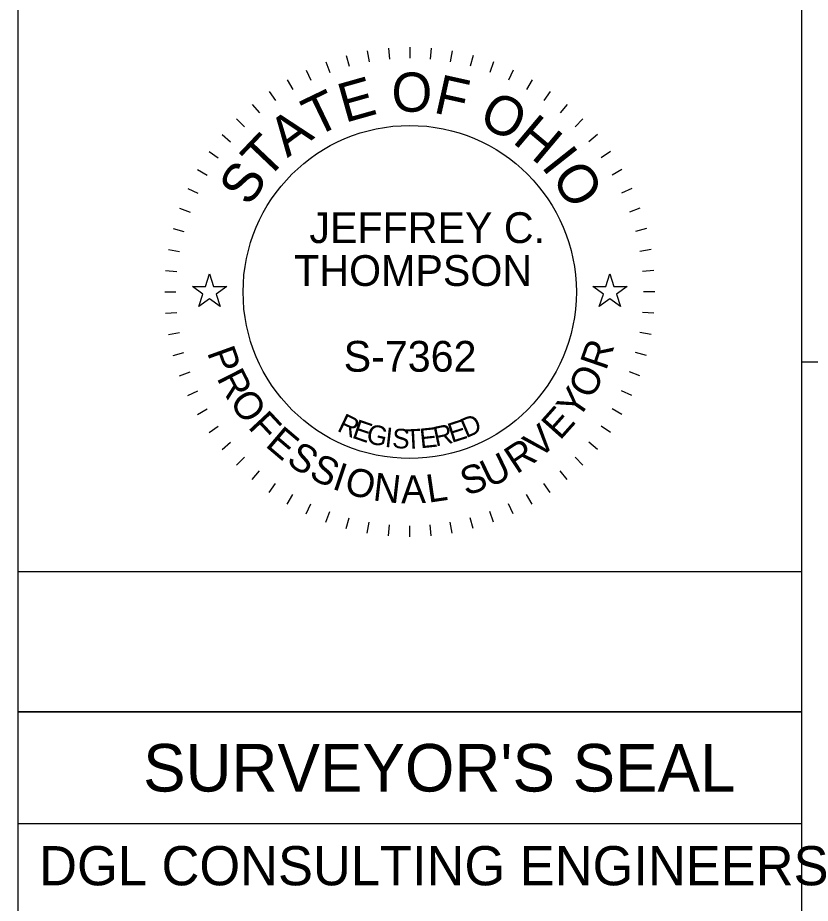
# Model space of a CAD drawing. Extents: x -10.5 to 54.7, y 0 to 22.
# Drawn here: x 29.2 to 32.03, y 3.066 to 6.23 of the extents above; entities that cross this region are included whole.
import ezdxf

# ---------------------------------------------------------------- set-up
doc = ezdxf.new("R2010")
doc.units = 0
for name, color, linetype in [('Default', 7, 'Continuous'), ('SH_Border', 7, 'Continuous'), ('SH_Data', 7, 'Continuous')]:
    doc.layers.add(name, color=color, linetype=linetype)

msp = doc.modelspace()

# ---------------------------------------------------------------- linework, layer by layer
at = {"layer": 'Default'}
for points in [[(29.8236, 5.27), (29.8705, 5.27), (29.885, 5.3145), (29.8995, 5.27), (29.9464, 5.27), (29.9085, 5.2424), (29.923, 5.1978), (29.885, 5.2254), (29.847, 5.1978), (29.8615, 5.2424)], [(31.2536, 5.27), (31.3005, 5.27), (31.315, 5.3145), (31.3295, 5.27), (31.3764, 5.27), (31.3385, 5.2424), (31.353, 5.1978), (31.315, 5.2254), (31.277, 5.1978), (31.2915, 5.2424)]]:
    msp.add_lwpolyline(points, close=True, dxfattribs=at)
at = {"layer": 'SH_Border'}
for p, q in [((32, 0.5), (32, 21.5)), ((32, 5), (33.5, 5))]:
    msp.add_line(p, q, dxfattribs=at)
at = {"layer": 'SH_Data'}
for p, q in [((29.2, 7), (29.2, 3.75)), ((32, 3.75), (32, 7)), ((30.4481, 6.1117), (30.455, 6.0723)), ((30.5237, 6.1217), (30.5272, 6.0818)), ((30.6, 6.125), (30.6, 6.085)), ((30.6763, 6.1217), (30.6728, 6.0818)), ((30.7519, 6.1117), (30.745, 6.0723)), ((30.3735, 6.0952), (30.3839, 6.0565)), ((30.8265, 6.0952), (30.8161, 6.0565)), ((30.3007, 6.0722), (30.3144, 6.0346)), ((30.8993, 6.0722), (30.8856, 6.0346)), ((30.2302, 6.043), (30.2471, 6.0068)), ((30.9698, 6.043), (30.9529, 6.0068)), ((30.1625, 6.0078), (30.1825, 5.9731)), ((31.0375, 6.0078), (31.0175, 5.9731)), ((30.0981, 5.9668), (30.1211, 5.934)), ((31.1019, 5.9668), (31.0789, 5.934)), ((30.0376, 5.9203), (30.0633, 5.8896)), ((31.1624, 5.9203), (31.1367, 5.8896)), ((29.9813, 5.8687), (30.0096, 5.8404)), ((31.2187, 5.8687), (31.1904, 5.8404)), ((29.9297, 5.8124), (29.9604, 5.7867)), ((31.2703, 5.8124), (31.2396, 5.7867)), ((29.8832, 5.7519), (29.916, 5.7289)), ((31.3168, 5.7519), (31.284, 5.7289)), ((29.8422, 5.6875), (29.8769, 5.6675)), ((31.3578, 5.6875), (31.3231, 5.6675)), ((29.807, 5.6198), (29.8432, 5.6029)), ((31.393, 5.6198), (31.3568, 5.6029)), ((29.7778, 5.5493), (29.8154, 5.5356)), ((31.4222, 5.5493), (31.3846, 5.5356)), ((29.7548, 5.4765), (29.7935, 5.4661)), ((31.4452, 5.4765), (31.4065, 5.4661)), ((29.7383, 5.4019), (29.7777, 5.395)), ((31.4617, 5.4019), (31.4223, 5.395)), ((29.7283, 5.3263), (29.7682, 5.3228)), ((31.4717, 5.3263), (31.4318, 5.3228)), ((29.725, 5.25), (29.765, 5.25)), ((31.475, 5.25), (31.435, 5.25)), ((29.7283, 5.1737), (29.7682, 5.1772)), ((31.4717, 5.1737), (31.4318, 5.1772)), ((29.7383, 5.0981), (29.7777, 5.105)), ((31.4617, 5.0981), (31.4223, 5.105)), ((29.7548, 5.0235), (29.7935, 5.0339)), ((31.4452, 5.0235), (31.4065, 5.0339)), ((29.7778, 4.9507), (29.8154, 4.9644)), ((31.4222, 4.9507), (31.3846, 4.9644)), ((29.807, 4.8802), (29.8432, 4.8971)), ((31.393, 4.8802), (31.3568, 4.8971)), ((29.8422, 4.8125), (29.8769, 4.8325)), ((31.3578, 4.8125), (31.3231, 4.8325)), ((29.8832, 4.7481), (29.916, 4.7711)), ((31.3168, 4.7481), (31.284, 4.7711)), ((29.9297, 4.6876), (29.9604, 4.7133)), ((31.2703, 4.6876), (31.2396, 4.7133)), ((29.9813, 4.6313), (30.0096, 4.6596)), ((31.2187, 4.6313), (31.1904, 4.6596)), ((30.0376, 4.5797), (30.0633, 4.6104)), ((31.1624, 4.5797), (31.1367, 4.6104)), ((30.0981, 4.5332), (30.1211, 4.566)), ((31.1019, 4.5332), (31.0789, 4.566)), ((30.1625, 4.4922), (30.1825, 4.5269)), ((31.0375, 4.4922), (31.0175, 4.5269)), ((30.2302, 4.457), (30.2471, 4.4932)), ((30.3007, 4.4278), (30.3144, 4.4654)), ((30.8993, 4.4278), (30.8856, 4.4654)), ((30.9698, 4.457), (30.9529, 4.4932)), ((30.3735, 4.4048), (30.3839, 4.4435)), ((30.8265, 4.4048), (30.8161, 4.4435)), ((30.4481, 4.3883), (30.455, 4.4277)), ((30.5237, 4.3783), (30.5272, 4.4182)), ((30.6, 4.375), (30.6, 4.415)), ((30.6763, 4.3783), (30.6728, 4.4182)), ((30.7519, 4.3883), (30.745, 4.4277)), ((32, 3.75), (29.2, 3.75)), ((29.2, 3.75), (29.2, 0.5)), ((32, 0.5), (32, 3.75)), ((32, 3.35), (29.2, 3.35))]:
    msp.add_line(p, q, dxfattribs=at)
msp.add_lwpolyline([(32, 3.75), (32, 4.25), (29.2, 4.25), (29.2, 3.75)], close=True, dxfattribs=at)
msp.add_circle((30.6, 5.25), 0.595, dxfattribs=at)

# ---------------------------------------------------------------- texts
for s, height, rotation, p in [('E', 0.14, 15.7571, (30.3684, 5.8538)), ('O', 0.14, 359.7812, (30.5347, 5.8943)), ('F', 0.14, 347.4362, (30.6811, 5.8917)), ('T', 0.14, 25.7167, (30.2616, 5.8018)), ('O', 0.14, 332.2586, (30.8398, 5.8515)), ('A', 0.14, 36.4747, (30.1634, 5.7281)), ('H', 0.14, 319.9136, (30.9632, 5.7861)), ('T', 0.14, 46.4344, (30.0883, 5.6464)), ('I', 0.14, 308.367, (31.0665, 5.6983)), ('S', 0.14, 57.1924, (30.0281, 5.5514)), ('O', 0.14, 303.1491, (31.1021, 5.6589)), ('R', 0.1, 70.983, (31.3009, 4.9667)), ('P', 0.1, 289.7431, (29.8753, 5.0341)), ('R', 0.1, 296.9802, (29.9093, 4.9427)), ('O', 0.1, 62.7428, (31.2501, 4.8633)), ('Y', 0.1, 55.5058, (31.2, 4.79)), ('O', 0.1, 304.7158, (29.9532, 4.8579)), ('E', 0.1, 48.2687, (31.1366, 4.7173)), ('F', 0.1, 312.956, (30.0192, 4.7658)), ('R', 0.07, 334.487, (30.3375, 4.7551)), ('E', 0.07, 341.04, (30.3906, 4.7301)), ('E', 0.07, 17.6836, (30.7498, 4.7102)), ('D', 0.07, 23.3052, (30.801, 4.727)), ('V', 0.1, 41.0316, (31.0615, 4.6507)), ('E', 0.1, 319.6885, (30.0808, 4.7004)), ('G', 0.07, 347.4752, (30.4414, 4.7118)), ('I', 0.07, 353.7858, (30.5091, 4.6968)), ('S', 0.07, 356.8926, (30.5358, 4.6929)), ('T', 0.07, 3.0061, (30.5857, 4.6887)), ('E', 0.07, 6.0117, (30.6389, 4.6912)), ('R', 0.07, 11.9184, (30.6925, 4.6974)), ('R', 0.1, 33.296, (30.9815, 4.5973)), ('S', 0.1, 326.9255, (30.1554, 4.6385)), ('S', 0.1, 334.1626, (30.236, 4.5874)), ('U', 0.1, 25.5604, (30.8833, 4.5486)), ('I', 0.1, 341.3997, (30.3191, 4.5479)), ('O', 0.1, 345.1351, (30.3618, 4.5321)), ('S', 0.1, 18.3234, (30.8005, 4.5211)), ('N', 0.1, 353.3752, (30.466, 4.5055)), ('A', 0.1, 1.1108, (30.5692, 4.4943)), ('L', 0.1, 8.3479, (30.6664, 4.4967))]:
    msp.add_text(s, height=height, rotation=rotation, dxfattribs=at).set_placement(p)
for s, height, p in [('JEFFREY C.', 0.11, (30.2416, 5.4249)), ('THOMPSON', 0.11, (30.1873, 5.2716)), ('S-7362', 0.11, (30.3641, 4.9651)), ("SURVEYOR'S SEAL", 0.17, (29.6478, 3.465)), ('DGL CONSULTING ENGINEERS', 0.14, (29.2766, 3.13))]:
    msp.add_text(s, height=height, dxfattribs=at).set_placement(p)

doc.saveas('drawing.dxf')
